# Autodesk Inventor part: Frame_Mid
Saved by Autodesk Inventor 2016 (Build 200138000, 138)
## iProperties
Created: 2016-01
Part Number: Frame_Mid
Material: Generic
Document SubType Name: Modeling
Designer: John
Density: 1 g/cm^3
Appearance: Default
Author: John
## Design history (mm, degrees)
feature "SOLID1"
body "Solid1"
